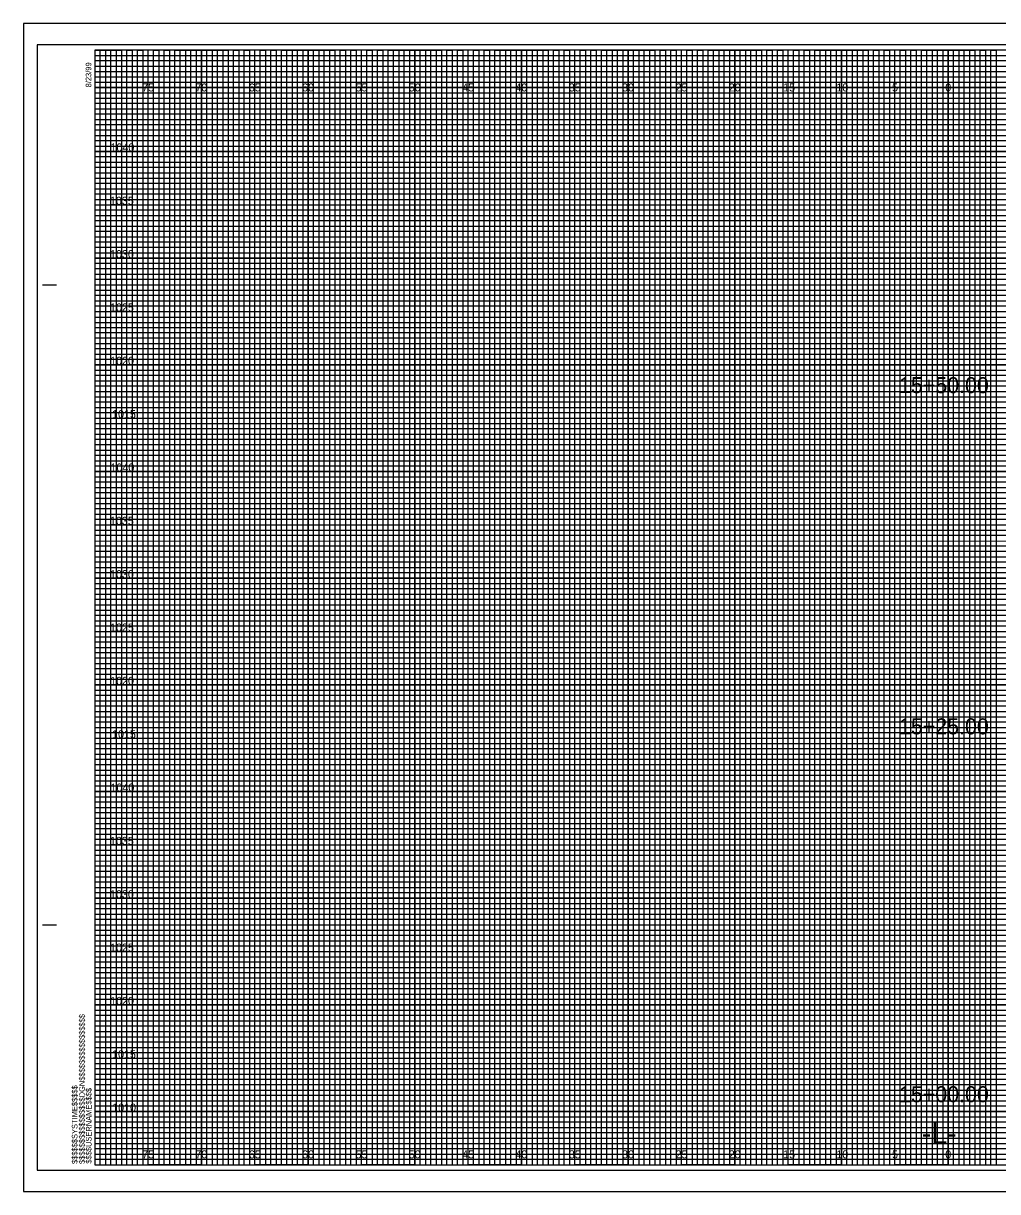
# Model space of a CAD drawing. Extents: x -7 to 178, y 548 to 657.
# Drawn here: x -6.7 to 84.6, y 547.5 to 657 of the extents above; entities that cross this region are included whole.
import ezdxf

# ---------------------------------------------------------------- set-up
doc = ezdxf.new("R2010")
doc.units = 0
for name, color, linetype in [('Exist Cross Section Cell', 7, 'Continuous'), ('Exist XS Center Line Elevation Label', 7, 'Continuous'), ('Exist XS Ground Line', 7, 'Continuous'), ('Prop CMT Concrete Structures', 7, 'Continuous'), ('Prop CMT DNC', 7, 'Continuous'), ('Prop CMT Guardrail Widen Shoulder', 7, 'Continuous'), ('Prop CMT Pvmt Course 1', 7, 'Continuous'), ('Prop CMT Pvmt Surface', 7, 'Continuous'), ('Prop CMT Shld Paved Course 1', 7, 'Continuous'), ('Prop CMT Slope Grass', 7, 'Continuous'), ('Prop CMT Subgrade Earthwork', 7, 'Continuous'), ('Prop XS Side Slope Text', 7, 'Continuous'), ('Typical Text Label CELL', 7, 'Continuous')]:
    doc.layers.add(name, color=color, linetype=linetype)

msp = doc.modelspace()

# ---------------------------------------------------------------- linework, layer by layer
at = {"layer": 'Exist XS Center Line Elevation Label'}
for points in [[(0, 654.5), (2.5, 654.5), (2.5, 550), (7.5, 550), (7.5, 654.5), (12.5, 654.5), (12.5, 550), (17.5, 550), (17.5, 654.5), (22.5, 654.5), (22.5, 550), (27.5, 550), (27.5, 654.5), (32.5, 654.5), (32.5, 550), (37.5, 550), (37.5, 654.5), (42.5, 654.5), (42.5, 550), (47.5, 550), (47.5, 654.5), (52.5, 654.5), (52.5, 550), (57.5, 550), (57.5, 654.5), (62.5, 654.5), (62.5, 550), (67.5, 550), (67.5, 654.5), (72.5, 654.5), (72.5, 550), (77.5, 550), (77.5, 654.5), (82.5, 654.5), (82.5, 550), (87.5, 550)], [(0, 652), (137.5, 652)], [(0, 642.5), (160, 642.5), (160, 647.5), (0, 647.5)], [(0, 632.5), (160, 632.5), (160, 637.5), (0, 637.5)], [(0, 622.5), (160, 622.5), (160, 627.5), (0, 627.5)], [(0, 612.5), (160, 612.5), (160, 617.5), (0, 617.5)], [(0, 602.5), (160, 602.5), (160, 607.5), (0, 607.5)], [(0, 592.5), (160, 592.5), (160, 597.5), (0, 597.5)], [(0, 582.5), (160, 582.5), (160, 587.5), (0, 587.5)], [(0, 572.5), (160, 572.5), (160, 577.5), (0, 577.5)], [(0, 562.5), (160, 562.5), (160, 567.5), (0, 567.5)], [(0, 552.5), (160, 552.5), (160, 557.5), (0, 557.5)]]:
    msp.add_lwpolyline(points, dxfattribs=at)
at = {"layer": 'Exist XS Ground Line'}
for p, q in [((5, 654.5), (0, 654.5)), ((5, 550), (5, 654.5)), ((15, 654.5), (10, 654.5)), ((10, 654.5), (10, 550)), ((15, 550), (15, 654.5)), ((25, 654.5), (20, 654.5)), ((20, 654.5), (20, 550)), ((25, 550), (25, 654.5)), ((35, 654.5), (30, 654.5)), ((30, 654.5), (30, 550)), ((35, 550), (35, 654.5)), ((45, 654.5), (40, 654.5)), ((40, 654.5), (40, 550)), ((45, 550), (45, 654.5)), ((55, 654.5), (50, 654.5)), ((50, 654.5), (50, 550)), ((55, 550), (55, 654.5)), ((65, 654.5), (60, 654.5)), ((60, 654.5), (60, 550)), ((65, 550), (65, 654.5)), ((75, 654.5), (70, 654.5)), ((70, 654.5), (70, 550)), ((75, 550), (75, 654.5)), ((85, 654.5), (80, 654.5)), ((80, 654.5), (80, 550)), ((10, 550), (5, 550)), ((20, 550), (15, 550)), ((30, 550), (25, 550)), ((40, 550), (35, 550)), ((50, 550), (45, 550)), ((60, 550), (55, 550)), ((70, 550), (65, 550)), ((80, 550), (75, 550))]:
    msp.add_line(p, q, dxfattribs=at)
for points in [[(0, 650), (160, 650), (160, 645), (0, 645)], [(0, 640), (160, 640), (160, 635), (0, 635)], [(0, 630), (160, 630), (160, 625), (0, 625)], [(0, 620), (160, 620), (160, 615), (0, 615)], [(0, 610), (160, 610), (160, 605), (0, 605)], [(0, 600), (160, 600), (160, 595), (0, 595)], [(0, 590), (160, 590), (160, 585), (0, 585)], [(0, 580), (160, 580), (160, 575), (0, 575)], [(0, 570), (160, 570), (160, 565), (0, 565)], [(0, 560), (160, 560), (160, 555), (0, 555)]]:
    msp.add_lwpolyline(points, dxfattribs=at)
at = {"layer": 'Prop CMT Concrete Structures'}
for p, q in [((5, 550), (5, 654.5)), ((10, 550), (10, 654.5)), ((15, 550), (15, 654.5)), ((20, 550), (20, 654.5)), ((25, 550), (25, 654.5)), ((30, 550), (30, 654.5)), ((35, 550), (35, 654.5)), ((40, 550), (40, 654.5)), ((45, 550), (45, 654.5)), ((50, 550), (50, 654.5)), ((55, 550), (55, 654.5)), ((60, 550), (60, 654.5)), ((65, 550), (65, 654.5)), ((70, 550), (70, 654.5)), ((75, 550), (75, 654.5)), ((80, 550), (80, 654.5)), ((0, 650), (160, 650)), ((0, 645), (160, 645)), ((0, 640), (160, 640)), ((0, 635), (160, 635)), ((0, 630), (160, 630)), ((0, 625), (160, 625)), ((0, 620), (160, 620)), ((0, 615), (160, 615)), ((0, 610), (160, 610)), ((0, 605), (160, 605)), ((0, 600), (160, 600)), ((0, 595), (160, 595)), ((0, 590), (160, 590)), ((0, 585), (160, 585)), ((0, 580), (160, 580)), ((0, 575), (160, 575)), ((0, 570), (160, 570)), ((0, 565), (160, 565)), ((0, 560), (160, 560)), ((0, 555), (160, 555))]:
    msp.add_line(p, q, dxfattribs=at)
at = {"layer": 'Prop CMT Guardrail Widen Shoulder'}
for p, q in [((161.65, 657), (-6.7, 657)), ((-6.7, 657), (-6.7, 547.5)), ((-6.7, 547.5), (161.65, 547.5))]:
    msp.add_line(p, q, dxfattribs=at)
at = {"layer": 'Prop CMT Pvmt Course 1'}
msp.add_lwpolyline([(-6.7, 547.5), (161.65, 547.5), (161.65, 657), (-6.7, 657)], close=True, dxfattribs=at)
at = {"layer": 'Prop CMT Pvmt Surface'}
for points in [[(0, 550), (0.5, 550), (0.5, 654.5), (1, 654.5), (1, 550)], [(1, 550), (1.5, 550), (1.5, 654.5), (2, 654.5), (2, 550)], [(2.5, 550), (3, 550), (3, 654.5), (3.5, 654.5), (3.5, 550)], [(3.5, 550), (4, 550), (4, 654.5), (4.5, 654.5), (4.5, 550)], [(5, 550), (5.5, 550), (5.5, 654.5), (6, 654.5), (6, 550)], [(6, 550), (6.5, 550), (6.5, 654.5), (7, 654.5), (7, 550)], [(7.5, 550), (8, 550), (8, 654.5), (8.5, 654.5), (8.5, 550)], [(8.5, 550), (9, 550), (9, 654.5), (9.5, 654.5), (9.5, 550)], [(10, 550), (10.5, 550), (10.5, 654.5), (11, 654.5), (11, 550)], [(11, 550), (11.5, 550), (11.5, 654.5), (12, 654.5), (12, 550)], [(12.5, 550), (13, 550), (13, 654.5), (13.5, 654.5), (13.5, 550)], [(13.5, 550), (14, 550), (14, 654.5), (14.5, 654.5), (14.5, 550)], [(15, 550), (15.5, 550), (15.5, 654.5), (16, 654.5), (16, 550)], [(16, 550), (16.5, 550), (16.5, 654.5), (17, 654.5), (17, 550)], [(17.5, 550), (18, 550), (18, 654.5), (18.5, 654.5), (18.5, 550)], [(18.5, 550), (19, 550), (19, 654.5), (19.5, 654.5), (19.5, 550)], [(20, 550), (20.5, 550), (20.5, 654.5), (21, 654.5), (21, 550)], [(21, 550), (21.5, 550), (21.5, 654.5), (22, 654.5), (22, 550)], [(22.5, 550), (23, 550), (23, 654.5), (23.5, 654.5), (23.5, 550)], [(23.5, 550), (24, 550), (24, 654.5), (24.5, 654.5), (24.5, 550)], [(25, 550), (25.5, 550), (25.5, 654.5), (26, 654.5), (26, 550)], [(26, 550), (26.5, 550), (26.5, 654.5), (27, 654.5), (27, 550)], [(27.5, 550), (28, 550), (28, 654.5), (28.5, 654.5), (28.5, 550)], [(28.5, 550), (29, 550), (29, 654.5), (29.5, 654.5), (29.5, 550)], [(30, 550), (30.5, 550), (30.5, 654.5), (31, 654.5), (31, 550)], [(31, 550), (31.5, 550), (31.5, 654.5), (32, 654.5), (32, 550)], [(32.5, 550), (33, 550), (33, 654.5), (33.5, 654.5), (33.5, 550)], [(33.5, 550), (34, 550), (34, 654.5), (34.5, 654.5), (34.5, 550)], [(35, 550), (35.5, 550), (35.5, 654.5), (36, 654.5), (36, 550)], [(36, 550), (36.5, 550), (36.5, 654.5), (37, 654.5), (37, 550)], [(37.5, 550), (38, 550), (38, 654.5), (38.5, 654.5), (38.5, 550)], [(38.5, 550), (39, 550), (39, 654.5), (39.5, 654.5), (39.5, 550)], [(40, 550), (40.5, 550), (40.5, 654.5), (41, 654.5), (41, 550)], [(41, 550), (41.5, 550), (41.5, 654.5), (42, 654.5), (42, 550)], [(42.5, 550), (43, 550), (43, 654.5), (43.5, 654.5), (43.5, 550)], [(43.5, 550), (44, 550), (44, 654.5), (44.5, 654.5), (44.5, 550)], [(45, 550), (45.5, 550), (45.5, 654.5), (46, 654.5), (46, 550)], [(46, 550), (46.5, 550), (46.5, 654.5), (47, 654.5), (47, 550)], [(47.5, 550), (48, 550), (48, 654.5), (48.5, 654.5), (48.5, 550)], [(48.5, 550), (49, 550), (49, 654.5), (49.5, 654.5), (49.5, 550)], [(50, 550), (50.5, 550), (50.5, 654.5), (51, 654.5), (51, 550)], [(51, 550), (51.5, 550), (51.5, 654.5), (52, 654.5), (52, 550)], [(52.5, 550), (53, 550), (53, 654.5), (53.5, 654.5), (53.5, 550)], [(53.5, 550), (54, 550), (54, 654.5), (54.5, 654.5), (54.5, 550)], [(55, 550), (55.5, 550), (55.5, 654.5), (56, 654.5), (56, 550)], [(56, 550), (56.5, 550), (56.5, 654.5), (57, 654.5), (57, 550)], [(57.5, 550), (58, 550), (58, 654.5), (58.5, 654.5), (58.5, 550)], [(58.5, 550), (59, 550), (59, 654.5), (59.5, 654.5), (59.5, 550)], [(60, 550), (60.5, 550), (60.5, 654.5), (61, 654.5), (61, 550)], [(61, 550), (61.5, 550), (61.5, 654.5), (62, 654.5), (62, 550)], [(62.5, 550), (63, 550), (63, 654.5), (63.5, 654.5), (63.5, 550)], [(63.5, 550), (64, 550), (64, 654.5), (64.5, 654.5), (64.5, 550)], [(65, 550), (65.5, 550), (65.5, 654.5), (66, 654.5), (66, 550)], [(66, 550), (66.5, 550), (66.5, 654.5), (67, 654.5), (67, 550)], [(67.5, 550), (68, 550), (68, 654.5), (68.5, 654.5), (68.5, 550)], [(68.5, 550), (69, 550), (69, 654.5), (69.5, 654.5), (69.5, 550)], [(70, 550), (70.5, 550), (70.5, 654.5), (71, 654.5), (71, 550)], [(71, 550), (71.5, 550), (71.5, 654.5), (72, 654.5), (72, 550)], [(72.5, 550), (73, 550), (73, 654.5), (73.5, 654.5), (73.5, 550)], [(73.5, 550), (74, 550), (74, 654.5), (74.5, 654.5), (74.5, 550)], [(75, 550), (75.5, 550), (75.5, 654.5), (76, 654.5), (76, 550)], [(76, 550), (76.5, 550), (76.5, 654.5), (77, 654.5), (77, 550)], [(77.5, 550), (78, 550), (78, 654.5), (78.5, 654.5), (78.5, 550)], [(78.5, 550), (79, 550), (79, 654.5), (79.5, 654.5), (79.5, 550)], [(80, 550), (80.5, 550), (80.5, 654.5), (81, 654.5), (81, 550)], [(81, 550), (81.5, 550), (81.5, 654.5), (82, 654.5), (82, 550)], [(82.5, 550), (83, 550), (83, 654.5), (83.5, 654.5), (83.5, 550)], [(83.5, 550), (84, 550), (84, 654.5), (84.5, 654.5), (84.5, 550)]]:
    msp.add_lwpolyline(points, dxfattribs=at)
at = {"layer": 'Prop CMT Shld Paved Course 1'}
for p, q in [((0, 654), (130, 654)), ((130, 653.49), (0, 653.49)), ((0, 653.49), (0, 653)), ((0, 653), (130, 653)), ((130, 652.45), (0, 652.45)), ((0, 652.45), (0, 651.5)), ((0, 651.5), (160, 651.5))]:
    msp.add_line(p, q, dxfattribs=at)
for points in [[(0, 651), (135, 651), (160, 651), (160, 651), (0, 651)], [(0, 650.5), (160, 650.5), (160, 649.5), (0, 649.5)], [(0, 649), (160, 649), (160, 648.5), (0, 648.49)], [(0, 648), (160, 648), (160, 647), (0, 647)], [(0, 646.5), (160, 646.5), (160, 646), (0, 646)], [(0, 645.5), (160, 645.5), (160, 644.5), (0, 644.5)], [(0, 644), (160, 644), (160, 643.5), (0, 643.5)], [(0, 643), (160, 643), (160, 642), (0, 642)], [(0, 641.5), (160, 641.5), (160, 641), (0, 641)], [(0, 640.5), (160, 640.5), (160, 639.5), (0, 639.5)], [(0, 639), (160, 639), (160, 638.5), (0, 638.5)], [(0, 638), (160, 638), (160, 636.98), (160, 636.5), (160, 636), (0, 636)], [(0, 637), (160, 637), (160, 636.5), (0, 636.5)], [(0, 635.5), (160, 635.5), (160, 634.5), (0, 634.51)], [(0, 634.51), (160, 634.5), (160, 634), (0, 634)], [(0, 633.5), (160, 633.5), (160, 633), (0, 633)], [(0, 632), (160, 632), (160, 631.5), (0, 631.5)], [(0, 631), (160, 631), (160, 630.5), (0, 630.5)], [(-0.04, 629.45), (160, 629.45), (160, 628.94), (-0.04, 628.94)], [(0, 628.5), (160, 628.5), (160, 628), (0, 628)], [(0, 627), (160, 627), (160, 626.5), (0, 626.5)], [(0, 626), (160, 626), (160, 625.5), (0, 625.5)], [(0, 624.5), (160, 624.5), (160, 624), (0, 624)], [(0, 623.5), (160, 623.5), (160, 623), (0, 623)], [(0, 622), (160, 622), (160, 621.5), (0, 621.5)], [(0, 621), (160, 621), (160, 620.5), (0, 620.5)], [(0, 619.5), (160, 619.5), (160, 618.99), (0, 619)], [(0, 618.5), (160, 618.5), (160, 618), (0, 618)], [(0, 617), (160, 617), (160, 616.5), (0, 616.5)], [(0, 616), (160, 616), (160, 615.5), (0, 615.5)], [(0, 614.5), (160, 614.5), (160, 614), (0, 614)], [(0, 613.5), (160, 613.5), (160, 613), (0, 613)], [(0, 612), (160, 612), (160, 611.5), (0, 611.5)], [(0, 611), (160, 611), (160, 610.5), (0, 610.5)], [(0, 609.5), (160, 609.5), (160, 609), (0, 609)], [(0, 608.5), (160.03, 608.46), (160, 608), (0, 608)], [(0, 607), (160, 607), (160, 606.5), (0, 606.5)], [(0, 606), (160, 606), (160, 605.5), (0, 605.5)], [(0, 604.5), (160, 604.5), (160, 604), (0, 604)], [(0, 603.5), (160, 603.5), (160, 603), (0, 603)], [(0, 602), (160, 602), (160, 601.5), (0, 601.5)], [(0, 601), (160, 601), (160, 600.5), (0, 600.5)], [(0, 599.5), (160, 599.5), (160, 599), (0, 599)], [(0, 598.5), (160, 598.5), (160, 598), (0, 598)], [(0, 597), (160, 597), (160, 596.5), (0, 596.5)], [(0, 596), (160, 596), (160, 595.5), (0, 595.5)], [(0, 594.5), (160, 594.5), (160, 594), (0, 594)], [(0, 593.5), (160, 593.5), (160, 593), (0, 593)], [(0, 592), (160, 592), (160, 591.5), (0, 591.5)], [(0, 591), (160, 591), (160, 590.5), (0, 590.5)], [(0, 589.5), (160, 589.5), (160, 588.99), (0, 589)], [(0, 588.5), (160, 588.5), (160, 588), (0, 588)], [(0, 587), (160, 587), (160, 586.5), (0, 586.5)], [(0, 586), (160, 586), (160, 585.5), (0, 585.5)], [(0, 584.5), (160, 584.5), (160, 584), (0, 584)], [(0, 583.5), (160, 583.5), (160, 583), (0, 583)], [(0, 582), (160, 582), (160, 581.5), (0, 581.5)], [(0, 581), (160, 581), (160, 580.5), (0, 580.5)], [(0, 579.5), (160, 579.5), (160, 579), (0, 579)], [(0, 578.5), (160.03, 578.46), (160, 578), (0, 578)], [(0, 577), (160, 577), (160, 576.5), (0, 576.5)], [(0, 576), (160, 576), (160, 575.5), (0, 575.5)], [(0, 574.5), (160, 574.5), (160, 574), (0, 574)], [(0, 573.5), (160, 573.5), (160, 573), (0, 573)], [(0, 572), (160, 572), (160, 571.5), (0, 571.5)], [(0, 571), (160, 571), (160, 570.5), (0, 570.5)], [(0, 569.5), (160, 569.5), (160, 569), (0, 569)], [(0, 568.5), (160, 568.5), (160, 568), (0, 568)], [(0, 567), (160, 567), (160, 566.5), (0, 566.5)], [(0, 566), (160, 566), (160, 565.5), (0, 565.5)], [(0, 564.5), (160, 564.5), (160, 564), (0, 564)], [(0, 563.5), (160, 563.5), (160, 563), (0, 563)], [(0, 562), (160, 562), (160, 561.5), (0, 561.5)], [(0, 561), (160, 561), (160, 560.5), (0, 560.5)], [(0, 559.5), (160, 559.5), (160, 559), (0, 559)], [(0, 558.5), (160, 558.5), (160, 558), (0, 558)], [(0, 557), (160, 557), (160, 556.5), (0, 556.5)], [(0, 556), (160, 556), (160, 555.5), (0, 555.5)], [(0, 554.5), (160, 554.5), (160, 554), (0, 554)], [(0, 553.5), (160, 553.5), (160, 553), (0, 553)], [(0, 552), (160, 552), (160, 551.5), (0, 551.5)], [(0, 551), (160, 551), (160, 550.5), (0, 550.5)]]:
    msp.add_lwpolyline(points, dxfattribs=at)
at = {"layer": 'Prop CMT Slope Grass'}
msp.add_lwpolyline([(-5.4, 549.5), (161.2, 549.5), (161.2, 655), (-5.4, 655)], close=True, dxfattribs=at)
at = {"layer": 'Prop CMT Subgrade Earthwork'}
for p, q in [((-4.9, 632.5), (-3.65, 632.5)), ((-4.85, 632.5), (-3.6, 632.5)), ((-4.9, 572.5), (-3.65, 572.5)), ((-4.85, 572.5), (-3.6, 572.5)), ((0, 550), (0, 550)), ((0, 550), (0, 550)), ((0, 550), (0, 550)), ((0, 550), (0, 550)), ((0, 550), (0, 550)), ((0, 550), (0, 550)), ((0, 550), (0, 550))]:
    msp.add_line(p, q, dxfattribs=at)
msp.add_lwpolyline([(160, 654.5), (0, 654.5), (0, 550), (160, 550)], close=True, dxfattribs=at)

# ---------------------------------------------------------------- texts
at = {"layer": 'Exist Cross Section Cell'}
for s, p in [('75', (4.44, 650.62)), ('70', (9.43, 650.62)), ('65', (14.44, 650.62)), ('60', (19.43, 650.62)), ('55', (24.44, 650.62)), ('50', (29.43, 650.62)), ('45', (34.44, 650.62)), ('40', (39.43, 650.62)), ('35', (44.44, 650.62)), ('30', (49.43, 650.62)), ('25', (54.44, 650.62)), ('20', (59.43, 650.62)), ('15', (64.53, 650.62)), ('10', (69.52, 650.62)), ('5', (74.74, 650.62)), ('0', (79.73, 650.62)), ('0', (79.73, 650.62)), ('75', (4.44, 550.62)), ('70', (9.43, 550.62)), ('65', (14.44, 550.62)), ('60', (19.43, 550.62)), ('55', (24.44, 550.62)), ('50', (29.43, 550.62)), ('45', (34.44, 550.62)), ('40', (39.43, 550.62)), ('35', (44.44, 550.62)), ('30', (49.43, 550.62)), ('25', (54.44, 550.62)), ('20', (59.43, 550.62)), ('15', (64.53, 550.62)), ('10', (69.52, 550.62)), ('5', (74.74, 550.62)), ('0', (79.73, 550.62)), ('0', (79.73, 550.62))]:
    msp.add_text(s, height=0.75, dxfattribs=at).set_placement(p)
at = {"layer": 'Prop CMT DNC'}
msp.add_text('-L-', height=2, dxfattribs=at).set_placement((77.53, 552))
at = {"layer": 'Prop CMT Subgrade Earthwork'}
for s, p in [('8/23/99', (-0.33, 651)), ('$$$$$$$$$$$$$$$$DGN$$$$$$$$$$$$$$$$', (-0.94, 550.09)), ('$$$$$$SYSTIME$$$$$', (-1.63, 550.09)), ('$$$$USERNAME$$$$', (-0.31, 550.12))]:
    msp.add_text(s, height=0.525, rotation=90, dxfattribs=at).set_placement(p)
at = {"layer": 'Prop XS Side Slope Text'}
for s, p in [('15+50.00', (75.39, 622.34)), ('15+25.00', (75.39, 590.36)), ('15+00.00', (75.39, 555.88))]:
    msp.add_text(s, height=1.5, dxfattribs=at).set_placement(p)
at = {"layer": 'Typical Text Label CELL'}
for s, p in [('1040', (1.47, 645)), ('1035', (1.42, 640)), ('1030', (1.43, 635)), ('1025', (1.43, 630)), ('1020', (1.44, 625)), ('1015', (1.62, 620)), ('1040', (1.47, 615)), ('1035', (1.42, 610)), ('1030', (1.43, 605)), ('1025', (1.43, 600)), ('1020', (1.44, 595)), ('1015', (1.62, 590)), ('1040', (1.47, 585)), ('1035', (1.42, 580)), ('1030', (1.43, 575)), ('1025', (1.43, 570)), ('1020', (1.44, 565)), ('1015', (1.62, 560)), ('1010', (1.63, 555))]:
    msp.add_text(s, height=0.75, dxfattribs=at).set_placement(p)

doc.saveas('drawing.dxf')
